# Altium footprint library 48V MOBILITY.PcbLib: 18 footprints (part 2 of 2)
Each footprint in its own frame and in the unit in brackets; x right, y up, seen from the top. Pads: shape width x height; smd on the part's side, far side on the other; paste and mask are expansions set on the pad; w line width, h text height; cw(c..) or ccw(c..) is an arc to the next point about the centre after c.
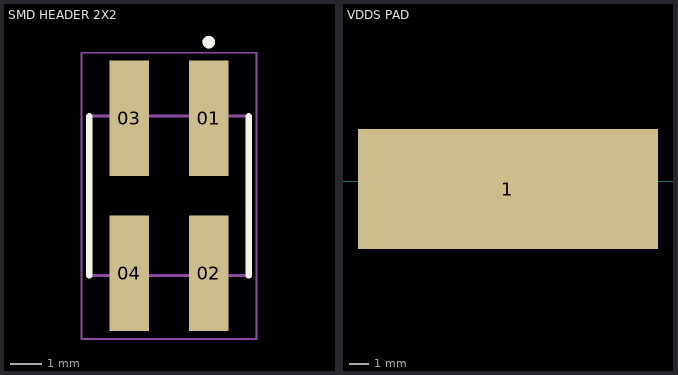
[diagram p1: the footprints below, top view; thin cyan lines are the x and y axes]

## SMD HEADER 2X2 [mm]
pads (4):
  rect 1.27x3.68 smd: 01(1269.873,1276.539) 02(1269.873,1271.589) 03(1267.333,1276.539) 04(1267.333,1271.589)
Top Overlay:
  circle w0.2: c1269.873,1278.964 r0.1
  lines w0.2: 1266.063,1271.524 1266.063,1276.604 ; 1271.143,1271.524 1271.143,1276.604
Mechanical 13:
  circle w0.2: c1269.873,1278.964 r0.1
  lines w0.1: 1266.063,1271.524 1266.063,1276.604 1271.143,1276.604 1271.143,1271.524 1266.063,1271.524
Mechanical 15:
  lines w0.05: 1265.813,1269.499 1265.813,1278.629 1271.393,1278.629 1271.393,1269.499 1265.813,1269.499
3D body "step_temp.STEP": height 9.91, standoff 0, extent 1266.063,1270.216 1271.143,1277.912

## VDDS PAD [mm]
pads (1):
  rect 15x6 smd: 1(53.661,-0.378)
